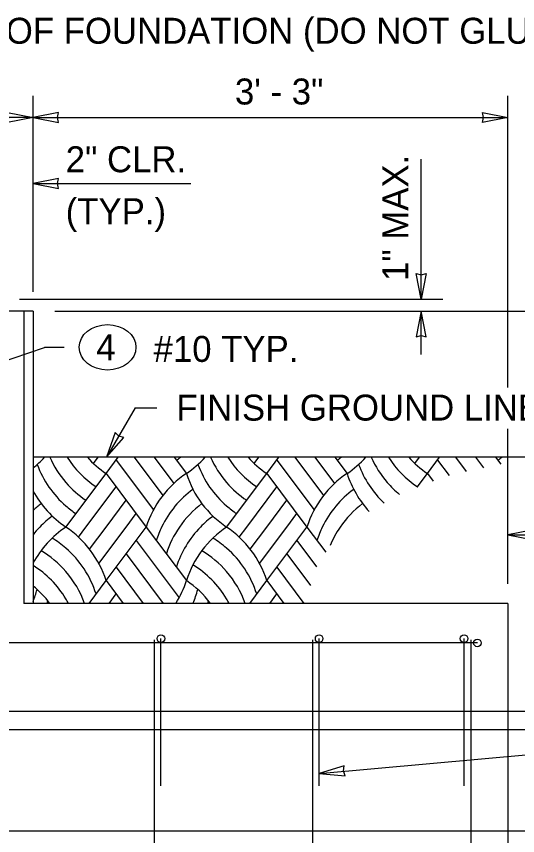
# Model space of a CAD drawing. Extents: x 99862 to 104211, y 98939 to 105076.
# Drawn here: x 100925 to 101234, y 100974 to 101479 of the extents above; entities that cross this region are included whole.
import ezdxf

# ---------------------------------------------------------------- set-up
doc = ezdxf.new("R2010")
doc.units = 0
for name, color, linetype in [('Level 10', 7, 'Continuous'), ('Level 15', 7, 'Continuous'), ('Level 2', 7, 'Continuous'), ('Level 20', 7, 'Continuous'), ('Level 5', 7, 'Continuous'), ('Level 6', 7, 'Continuous'), ('Level 7', 7, 'Continuous'), ('Level 9', 7, 'Continuous')]:
    doc.layers.add(name, color=color, linetype=linetype)

msp = doc.modelspace()

# ---------------------------------------------------------------- linework, layer by layer
at = {"layer": 'Level 10'}
for p, q in [((101209.03, 101093.04), (100888.47, 101093.04)), ((101009.91, 101094.9), (101009.91, 100423.65)), ((101014.03, 101004.9), (101014.03, 101095.65)), ((101107.41, 101094.9), (101107.41, 100423.65)), ((101111.53, 101004.9), (101111.53, 101095.65)), ((101200.78, 101004.9), (101200.78, 101095.65)), ((101204.9, 101094.9), (101204.9, 100423.65))]:
    msp.add_line(p, q, dxfattribs=at)
for centre in [(101014.03, 101095.65), (101111.53, 101095.65), (101200.78, 101095.65), (101209.03, 101093.04)]:
    msp.add_circle(centre, 2.34, dxfattribs=at)
at = {"layer": 'Level 15'}
for p, q in [((100935.28, 101309.4), (100935.28, 101430.07)), ((101227.78, 101290.74), (101227.78, 101430.07)), ((100935.28, 101416.74), (100860.83, 101416.74)), ((100935.28, 101416.74), (101227.78, 101416.74)), ((101174.44, 101304.82), (101174.44, 101391.09)), ((100935.28, 101376.07), (101032.39, 101376.07)), ((100926.94, 101304.82), (101187.78, 101304.82)), ((100948.61, 101297.4), (101361.11, 101297.4)), ((101174.44, 101270.74), (101174.44, 101297.4)), ((101227.78, 101250.48), (101227.78, 101290.74)), ((100895.72, 101259.26), (100942.4, 101275.05)), ((100954.4, 101275.05), (100942.4, 101275.05)), ((100998.22, 101237.95), (100980.59, 101207.4)), ((100998.22, 101237.95), (101011.56, 101237.95)), ((101227.78, 101129.4), (101227.78, 101224.98)), ((101227.78, 101159.6), (101272.78, 101159.6)), ((101111.57, 101012.66), (101256.7, 101025.61)), ((101292.71, 100976.97), (100905.73, 100976.97))]:
    msp.add_line(p, q, dxfattribs=at)
for points in [[(100980.59, 101207.4), (100991.12, 101219.48), (100988.09, 101220.39), (100985.78, 101222.56)], [(101111.57, 101012.67), (101127.53, 101011.17), (101126.49, 101014.17), (101126.91, 101017.31)]]:
    msp.add_lwpolyline(points, close=True, dxfattribs=at)
at = {"layer": 'Level 2'}
for p, q in [((100935.28, 101297.4), (100620.28, 101297.4)), ((100929.65, 101297.4), (100929.65, 101117.4)), ((100935.28, 101297.4), (100935.28, 101117.4)), ((101227.78, 101117.4), (100929.65, 101117.4)), ((101227.78, 101117.4), (101227.78, 100397.4))]:
    msp.add_line(p, q, dxfattribs=at)
at = {"layer": 'Level 20'}
msp.add_ellipse((100981.16, 101275.16), major_axis=(-17.5, 0), ratio=0.8, dxfattribs=at)
at = {"layer": 'Level 5'}
for p, q in [((101265.28, 101050.74), (101227.78, 101050.74)), ((101265.28, 101039.49), (101227.78, 101039.49))]:
    msp.add_line(p, q, dxfattribs=at)
at = {"layer": 'Level 6'}
for p, q in [((101227.78, 101050.74), (100822.78, 101050.74)), ((101227.78, 101039.49), (100822.78, 101039.49))]:
    msp.add_line(p, q, dxfattribs=at)
at = {"layer": 'Level 7'}
for points in [[(100935.28, 101416.74), (100919.55, 101413.65), (100920.28, 101416.74), (100919.55, 101419.82)], [(100935.28, 101416.74), (100951, 101413.65), (100950.27, 101416.74), (100951, 101419.82)], [(101227.78, 101416.74), (101212.05, 101413.65), (101212.78, 101416.74), (101212.05, 101419.82)], [(100935.28, 101376.07), (100951, 101372.99), (100950.27, 101376.07), (100951, 101379.15)], [(101174.44, 101304.82), (101171.36, 101320.55), (101174.44, 101319.82), (101177.53, 101320.55)], [(101174.44, 101297.4), (101171.36, 101281.68), (101174.44, 101282.41), (101177.53, 101281.68)], [(101227.78, 101159.6), (101243.5, 101156.51), (101242.77, 101159.6), (101243.5, 101162.68)]]:
    msp.add_lwpolyline(points, close=True, dxfattribs=at)
at = {"layer": 'Level 9'}
for p, q in [((101272.78, 101207.4), (100935.28, 101207.4)), ((100972.5, 101203.56), (100975.39, 101207.4)), ((100980.26, 101197.4), (100987.76, 101207.4)), ((100986.45, 101205.65), (101009.47, 101174.96)), ((100997.51, 101207.4), (101015.21, 101183.81)), ((101009.89, 101207.4), (101022, 101191.25)), ((101022.26, 101207.4), (101029.76, 101197.4)), ((101071.5, 101203.56), (101074.38, 101207.4)), ((101079.25, 101197.4), (101086.75, 101207.4)), ((101085.44, 101205.65), (101108.46, 101174.96)), ((101096.5, 101207.4), (101114.2, 101183.81)), ((101108.88, 101207.4), (101120.99, 101191.25)), ((101121.25, 101207.4), (101128.75, 101197.4)), ((101170.49, 101203.56), (101173.37, 101207.4)), ((101178.25, 101197.4), (101185.75, 101207.4)), ((101184.43, 101205.65), (101191.57, 101196.13)), ((101195.5, 101207.4), (101202.04, 101198.68)), ((101207.87, 101207.4), (101212.71, 101200.95)), ((101220.25, 101207.4), (101223.39, 101203.22)), ((100955.51, 101164.41), (100980.26, 101197.4)), ((100980.26, 101197.4), (101005.01, 101164.41)), ((101054.51, 101164.41), (101079.25, 101197.4)), ((101079.25, 101197.4), (101104, 101164.41)), ((101171.99, 101189.06), (101178.25, 101197.4)), ((101178.25, 101197.4), (101181.84, 101192.62)), ((100967.89, 101164.41), (100986.45, 101189.16)), ((101066.88, 101164.41), (101085.44, 101189.16)), ((100980.26, 101164.41), (100992.64, 101180.91)), ((101079.25, 101164.41), (101091.63, 101180.91)), ((100992.64, 101164.41), (100998.82, 101172.66)), ((101091.63, 101164.41), (101097.82, 101172.66)), ((100963.27, 101158.25), (100967.89, 101164.41)), ((100970.06, 101150.81), (100980.26, 101164.41)), ((100975.8, 101141.96), (100992.64, 101164.41)), ((100980.26, 101131.41), (101005.01, 101164.41)), ((101005.01, 101164.41), (101029.76, 101131.41)), ((101062.26, 101158.25), (101066.88, 101164.41)), ((101069.06, 101150.81), (101079.25, 101164.41)), ((101074.8, 101141.96), (101091.63, 101164.41)), ((101079.25, 101131.41), (101104, 101164.41)), ((101104, 101164.41), (101115.64, 101148.89)), ((100998.82, 101156.16), (101025.3, 101120.85)), ((101097.82, 101156.16), (101109.98, 101139.93)), ((100992.64, 101147.91), (101015.51, 101117.4)), ((101091.63, 101147.91), (101106.27, 101128.39)), ((100986.45, 101139.66), (101003.14, 101117.4)), ((101085.44, 101139.66), (101102.13, 101117.4)), ((100969.76, 101117.4), (100980.26, 101131.41)), ((100980.26, 101131.41), (100990.76, 101117.4)), ((101068.75, 101117.4), (101079.25, 101131.41)), ((101079.25, 101131.41), (101089.76, 101117.4)), ((100982.13, 101117.4), (100986.45, 101123.16)), ((101081.12, 101117.4), (101085.44, 101123.16))]:
    msp.add_line(p, q, dxfattribs=at)
for centre, start, end in [((100895.83, 101249.39), 309.0387, 317.9069), ((100996.64, 101224.64), 200.2432, 228.9599), ((101002.82, 101232.89), 204.0099, 220.9416), ((101009.01, 101241.14), 212.5895, 236.0964), ((101015.2, 101249.39), 222.0931, 236.0964), ((100988.64, 101257.63), 303.9036, 306.6728), ((100994.82, 101249.39), 303.9036, 317.9069), ((101095.63, 101224.64), 200.2432, 228.9599), ((101101.82, 101232.89), 204.0099, 220.9416), ((101108, 101241.14), 212.5895, 236.0964), ((101114.19, 101249.39), 222.0931, 236.0964), ((101087.63, 101257.63), 303.9036, 306.6728), ((101093.82, 101249.39), 303.9036, 317.9069), ((101194.62, 101224.64), 200.2432, 226.4818), ((101200.81, 101232.89), 204.0099, 220.9416), ((101206.99, 101241.14), 212.5895, 236.0964), ((101213.18, 101249.39), 222.0931, 236.0964), ((101186.62, 101257.63), 303.9036, 306.6728), ((101064.69, 101145.42), 123.9036, 162.3566), ((101089.44, 101216.39), 197.6434, 236.0964), ((101163.69, 101145.42), 123.9036, 162.3566), ((101188.43, 101216.39), 197.6434, 222.5429), ((101002.82, 101232.89), 220.9415, 236.0964), ((101070.88, 101137.17), 126.3063, 154.2266), ((101101.81, 101232.89), 220.9415, 236.0964), ((101169.87, 101137.17), 126.3063, 154.2266), ((101200.81, 101232.89), 220.9415, 230.5068), ((100990.45, 101216.39), 208.2473, 236.0964), ((100978.07, 101128.92), 127.1006, 133.1045), ((100996.63, 101224.64), 228.9599, 236.0964), ((101077.07, 101128.92), 127.1006, 145.4911), ((101095.63, 101224.64), 228.9599, 236.0964), ((101176.06, 101128.92), 127.1006, 145.4911), ((100984.26, 101120.68), 126.331, 135.7128), ((101083.25, 101120.68), 126.331, 135.7128), ((100990.45, 101112.43), 123.9036, 151.7527), ((100984.26, 101120.68), 135.7127, 141.4553), ((100920.58, 101112.43), 17.6434, 56.0963), ((101070.88, 101137.17), 154.2265, 162.3566), ((101077.07, 101128.92), 145.491, 162.3566), ((101083.25, 101120.68), 135.7127, 162.3566), ((101089.44, 101112.43), 123.9036, 162.3566), ((101019.57, 101112.43), 17.6434, 56.0963), ((101169.87, 101137.17), 154.2265, 162.3566), ((101176.06, 101128.92), 145.491, 157.3818), ((100914.39, 101104.18), 48.9597, 58.5465), ((101013.39, 101104.18), 48.9597, 58.5465), ((100908.21, 101095.93), 40.9413, 59.3021), ((100914.39, 101104.18), 17.6434, 48.9597), ((101007.2, 101095.93), 40.9413, 59.3021), ((101013.38, 101104.18), 17.6434, 48.9597), ((100902.02, 101087.68), 31.3316, 57.9233), ((100908.2, 101095.93), 20.0544, 40.9414), ((101001.01, 101087.68), 31.3316, 58.4874), ((101007.2, 101095.93), 20.0544, 40.9414), ((100895.83, 101079.43), 37.3264, 50.9613), ((100970.08, 101150.39), 328.2163, 342.3566), ((100994.82, 101079.43), 37.3264, 56.0964), ((100877.27, 101142.14), 337.8528, 345.0113), ((100976.26, 101142.14), 336.7345, 345.0113), ((100883.46, 101133.89), 344.7357, 346.3199), ((100902.02, 101087.68), 28.3355, 31.3317), ((100982.45, 101133.89), 344.7357, 346.3199), ((101001.01, 101087.68), 28.3355, 31.3317)]:
    msp.add_arc(centre, 62.63, start, end, dxfattribs=at)

# ---------------------------------------------------------------- texts
at = {"layer": 'Level 20'}
for s, rotation, p in [('OF FOUNDATION (DO NOT GLUE PVC STUBOUT)', 360, (100918.51, 101462.17)), ('1" MAX.', 90, (101166.44, 101316.02)), ('FINISH GROUND LINE', 0.0239, (101023.56, 101229.95))]:
    msp.add_text(s, height=16, rotation=rotation, dxfattribs=at).set_placement(p)
for s, p in [('3\' - 3"', (101059.64, 101424.74)), ('2" CLR.', (100955.4, 101382.99)), ('(TYP.)', (100955.4, 101350.99)), ('4', (100974.21, 101267.16)), ('#10 TYP.', (101009.55, 101266.15))]:
    msp.add_text(s, height=16, dxfattribs=at).set_placement(p)

doc.saveas('drawing.dxf')
